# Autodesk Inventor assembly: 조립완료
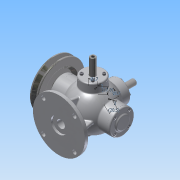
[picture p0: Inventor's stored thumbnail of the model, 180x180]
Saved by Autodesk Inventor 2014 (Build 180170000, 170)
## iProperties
Created: 2016-01
Part Number: 조립완료
Document SubType Name: Assembly
Designer: Administrator
Mass: 3770.67 g
Surface Area: 2410.99 cm^2
Volume: 903.657 cm^3
Density: 4.17267 g/cm^3
Author: Administrator
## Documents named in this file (17)
- C:\Users\Administrator\Desktop\360108V1014\조립완료.iam
- C:\Users\Administrator\Desktop\360108V1014\본체.ipt
- C:\Users\Administrator\Desktop\360108V1014\앞커버.ipt
- C:\Users\Administrator\Desktop\360108V1014\뒤커버.ipt
- C:\Users\Administrator\Desktop\360108V1014\베어링- 6202.ipt
- C:\Users\Administrator\Desktop\360108V1014\축.ipt
- C:\Users\Administrator\Desktop\360108V1014\본체커버.ipt
- C:\Users\Administrator\Desktop\360108V1014\볼트 M4x0.7.ipt
- C:\Users\Administrator\Desktop\360108V1014\슬라이드.ipt
- C:\Users\Administrator\Desktop\360108V1014\키-4x4.ipt
- C:\Users\Administrator\Desktop\360108V1014\오일실.ipt
- C:\Users\Administrator\Desktop\360108V1014\슬라이드 커버.ipt
- C:\Users\Administrator\Desktop\360108V1014\V-벨트풀리.ipt
- C:\Users\Administrator\Desktop\360108V1014\너트-M8x1.ipt
- C:\Users\Administrator\Desktop\360108V1014\와셔 8x17.ipt
- C:\Users\Administrator\Desktop\360108V1014\가변스프링.ipt
- C:\Users\Administrator\Desktop\360108V1014\가변스프링2.ipt
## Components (20 placed, 4 different names)
1. M4x0.7x12:5
2. V-벨트풀리:1 — 플러쉬:1, 각도:2
3. 가변스프링:1
4. 가변스프링2:1
5. M4x0.7x12:1
6. M4x0.7x12:2
7. M4x0.7x12:3
8. M4x0.7x12:4
9. M4x0.7x12:6
10. M4x0.7x12:7
11. M4x0.7x12:8
12. M4x0.7x12:9
13. M4x0.7x12:10
14. M4x0.7x12:11
15. M4x0.7x12:12
16. M4x0.7x12:13
17. M4x0.7x12:14
18. M4x0.7x12:15
19. M4x0.7x12:16
20. M4x0.7x12:17
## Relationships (2: Flush 1, Angle 1)
- 플러쉬:1 [Flush]: V-벨트풀리:1
- 각도:2 [Angle]: V-벨트풀리:1
